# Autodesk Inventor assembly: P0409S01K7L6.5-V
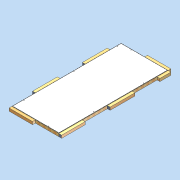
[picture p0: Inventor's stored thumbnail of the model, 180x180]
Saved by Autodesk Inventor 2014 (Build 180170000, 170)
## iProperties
Created: 2011-04
Part Number: P0409S01K7L6.5-V
Document SubType Name: Assembly
Designer: david.appleford
Description: 1w x 2.25w 01 Panel - 7 Locks 6.5 Lugs
Mass: 54000 g
Surface Area: 78852.4 cm^2
Volume: 263450 cm^3
Cost Center: £184.00
Density: 0.204973 g/cm^3
Justset: False
Title: 1w x 2.25w 01 Panel - 7 Locks 6.5 Lugs
Author: david.appleford
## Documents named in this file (5)
- C:\Documents and Settings\john.everitt\Local Settings\My Documents\Vault\Production MkII\VIRTUAL ELEMENTS\Virtual Walls\Virtual Timber + MgO\P0409S01K7L6.5-V.iam
- C:\Documents and Settings\john.everitt\Local Settings\My Documents\Vault\Production MkII\VIRTUAL ELEMENTS\Virtual Lugs\Superceded Lugs\LA02C3V.ipt
- C:\Documents and Settings\john.everitt\Local Settings\My Documents\Vault\Production MkII\VIRTUAL ELEMENTS\Virtual Lugs\Superceded Lugs\LA02M3V.ipt
- C:\Documents and Settings\john.everitt\Local Settings\My Documents\Vault\Production MkII\Virtual Elements\Virtual Walls\Virtual Timber + MgO\P0409S01K7-V.ipt
- C:\Documents and Settings\john.everitt\Local Settings\My Documents\Vault\Production MkII\VIRTUAL ELEMENTS\Virtual Lugs\Superceded Lugs\LA01C3V.ipt
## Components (8 placed, 4 different names)
1. P0409S01K7-V:1 — Mate:1, Flush:1, Flush:2, Mate:2, Flush:3, Flush:4, Mate:4, Flush:7, Flush:8, Mate:5, Mate:6, Flush:9, Flush:10, Mate:7, Flush:11, Mate:14, Flush:12, Flush:13
2. LA02C3V:1 — Mate:1, Flush:1, Flush:2, Mate:9, Mate:13
3. LA02C3V:2 — Mate:2, Flush:3, Flush:4
4. LA02C3V:3 — Mate:4, Flush:7, Flush:8
5. LA02M3V:5 — Mate:6, Flush:9, Mate:12
6. LA02M3V:2 — Mate:5, Flush:10, Mate:12, Mate:13
7. LA02M3V:4 — Mate:7, Flush:11, Mate:9
8. LA01C3V:1 — Mate:14, Flush:12, Flush:13
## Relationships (21: Flush 11, Mate 10)
- Mate:1: P0409S01K7-V:1 ↔ LA02C3V:1
- Flush:1: P0409S01K7-V:1 ↔ LA02C3V:1
- Flush:2: P0409S01K7-V:1 ↔ LA02C3V:1
- Mate:2: P0409S01K7-V:1 ↔ LA02C3V:2
- Flush:3: P0409S01K7-V:1 ↔ LA02C3V:2
- Flush:4: P0409S01K7-V:1 ↔ LA02C3V:2
- Mate:4: P0409S01K7-V:1 ↔ LA02C3V:3
- Flush:7: P0409S01K7-V:1 ↔ LA02C3V:3
- Flush:8: P0409S01K7-V:1 ↔ LA02C3V:3
- Mate:5: P0409S01K7-V:1 ↔ LA02M3V:2
- Mate:6: P0409S01K7-V:1 ↔ LA02M3V:5
- Flush:9: P0409S01K7-V:1 ↔ LA02M3V:5
- Flush:10: P0409S01K7-V:1 ↔ LA02M3V:2
- Mate:7: P0409S01K7-V:1 ↔ LA02M3V:4
- Flush:11: P0409S01K7-V:1 ↔ LA02M3V:4
- Mate:9: LA02C3V:1 ↔ LA02M3V:4
- Mate:12: LA02M3V:5 ↔ LA02M3V:2
- Mate:13: LA02C3V:1 ↔ LA02M3V:2
- Mate:14: P0409S01K7-V:1 ↔ LA01C3V:1
- Flush:12: P0409S01K7-V:1 ↔ LA01C3V:1
- Flush:13: P0409S01K7-V:1 ↔ LA01C3V:1
## Named parameters: t = 1 mm, Cl = 2 mm
